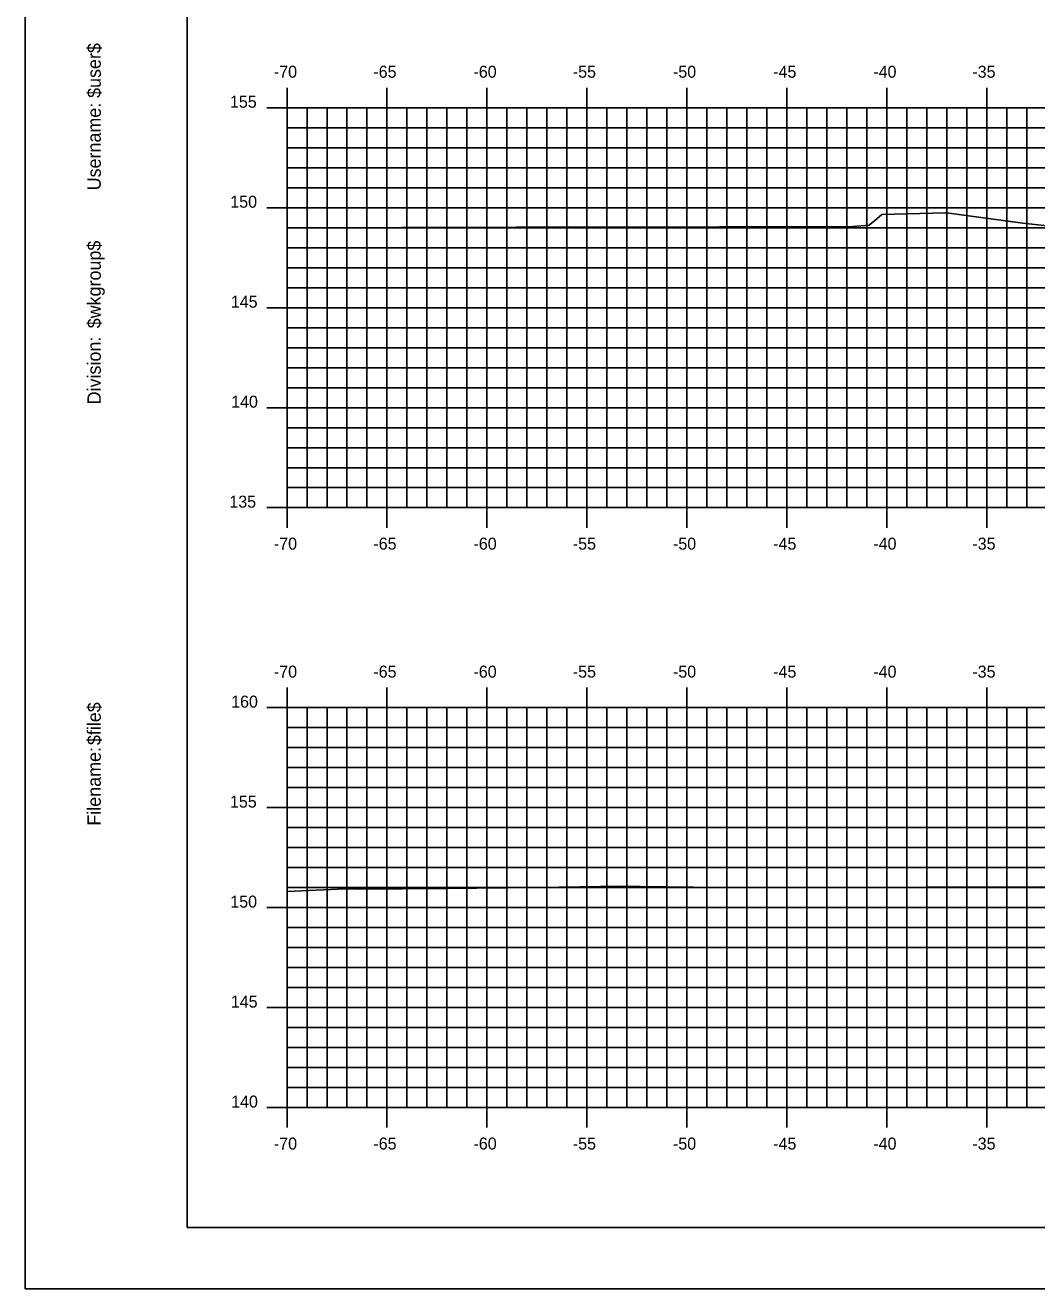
# Model space of a CAD drawing. Extents: x 850973 to 851145, y 365876 to 365986.
# Drawn here: x 850973.3 to 851023.9, y 365875.8 to 365939 of the extents above; entities that cross this region are included whole.
import ezdxf

# ---------------------------------------------------------------- set-up
doc = ezdxf.new("R2010")
doc.units = 0
for name, color, linetype in [('BORDER', 7, 'Continuous'), ('H_V ANNOTATION', 7, 'Continuous'), ('MAJOR', 7, 'Continuous'), ('MINOR', 7, 'Continuous'), ('PLOT BOUNDARY', 7, 'Continuous'), ('S_Roadway_Centerline', 7, 'Continuous')]:
    doc.layers.add(name, color=color, linetype=linetype)

msp = doc.modelspace()

# ---------------------------------------------------------------- linework, layer by layer
at = {"layer": 'BORDER'}
msp.add_lwpolyline([(850981.386, 365878.833), (851141.386, 365878.833), (851141.386, 365983.833), (850981.386, 365983.833)], close=True, dxfattribs=at)
at = {"layer": 'MAJOR'}
for p, q in [((850986.385, 365935.835), (850986.385, 365934.833)), ((850991.385, 365935.835), (850991.385, 365934.833)), ((850996.385, 365935.835), (850996.385, 365934.833)), ((851001.385, 365935.835), (851001.385, 365934.833)), ((851006.385, 365935.835), (851006.385, 365934.833)), ((851011.385, 365935.835), (851011.385, 365934.833)), ((851016.385, 365935.835), (851016.385, 365934.833)), ((851021.385, 365935.835), (851021.385, 365934.833)), ((850985.383, 365934.833), (850986.385, 365934.833)), ((850986.385, 365934.833), (851126.385, 365934.833)), ((850986.385, 365914.833), (850986.385, 365934.833)), ((850986.385, 365914.833), (850986.385, 365934.833)), ((850986.385, 365934.833), (851126.385, 365934.833)), ((850991.385, 365914.833), (850991.385, 365934.833)), ((850996.385, 365914.833), (850996.385, 365934.833)), ((851001.385, 365914.833), (851001.385, 365934.833)), ((851006.385, 365914.833), (851006.385, 365934.833)), ((851011.385, 365914.833), (851011.385, 365934.833)), ((851016.385, 365914.833), (851016.385, 365934.833)), ((851021.385, 365914.833), (851021.385, 365934.833)), ((850985.383, 365929.833), (850986.385, 365929.833)), ((850986.385, 365929.833), (851126.385, 365929.833)), ((850985.383, 365924.833), (850986.385, 365924.833)), ((850986.385, 365924.833), (851126.385, 365924.833)), ((850985.383, 365919.833), (850986.385, 365919.833)), ((850986.385, 365919.833), (851126.385, 365919.833)), ((850985.383, 365914.833), (850986.385, 365914.833)), ((850986.385, 365914.833), (851126.385, 365914.833)), ((850986.385, 365914.833), (851126.385, 365914.833)), ((850986.385, 365913.831), (850986.385, 365914.833)), ((850991.385, 365913.831), (850991.385, 365914.833)), ((850996.385, 365913.831), (850996.385, 365914.833)), ((851001.385, 365913.831), (851001.385, 365914.833)), ((851006.385, 365913.831), (851006.385, 365914.833)), ((851011.385, 365913.831), (851011.385, 365914.833)), ((851016.385, 365913.831), (851016.385, 365914.833)), ((851021.385, 365913.831), (851021.385, 365914.833)), ((850986.385, 365905.835), (850986.385, 365904.833)), ((850991.385, 365905.835), (850991.385, 365904.833)), ((850996.385, 365905.835), (850996.385, 365904.833)), ((851001.385, 365905.835), (851001.385, 365904.833)), ((851006.385, 365905.835), (851006.385, 365904.833)), ((851011.385, 365905.835), (851011.385, 365904.833)), ((851016.385, 365905.835), (851016.385, 365904.833)), ((851021.385, 365905.835), (851021.385, 365904.833)), ((850985.383, 365904.833), (850986.385, 365904.833)), ((850986.385, 365904.833), (851126.385, 365904.833)), ((850986.385, 365884.833), (850986.385, 365904.833)), ((850986.385, 365884.833), (850986.385, 365904.833)), ((850986.385, 365904.833), (851126.385, 365904.833)), ((850991.385, 365884.833), (850991.385, 365904.833)), ((850996.385, 365884.833), (850996.385, 365904.833)), ((851001.385, 365884.833), (851001.385, 365904.833)), ((851006.385, 365884.833), (851006.385, 365904.833)), ((851011.385, 365884.833), (851011.385, 365904.833)), ((851016.385, 365884.833), (851016.385, 365904.833)), ((851021.385, 365884.833), (851021.385, 365904.833)), ((850985.383, 365899.833), (850986.385, 365899.833)), ((850986.385, 365899.833), (851126.385, 365899.833)), ((850985.383, 365894.833), (850986.385, 365894.833)), ((850986.385, 365894.833), (851126.385, 365894.833)), ((850985.383, 365889.833), (850986.385, 365889.833)), ((850986.385, 365889.833), (851126.385, 365889.833)), ((850985.383, 365884.833), (850986.385, 365884.833)), ((850986.385, 365884.833), (851126.385, 365884.833)), ((850986.385, 365884.833), (851126.385, 365884.833)), ((850986.385, 365883.831), (850986.385, 365884.833)), ((850991.385, 365883.831), (850991.385, 365884.833)), ((850996.385, 365883.831), (850996.385, 365884.833)), ((851001.385, 365883.831), (851001.385, 365884.833)), ((851006.385, 365883.831), (851006.385, 365884.833)), ((851011.385, 365883.831), (851011.385, 365884.833)), ((851016.385, 365883.831), (851016.385, 365884.833)), ((851021.385, 365883.831), (851021.385, 365884.833))]:
    msp.add_line(p, q, dxfattribs=at)
at = {"layer": 'MINOR'}
for p, q in [((850987.385, 365914.833), (850987.385, 365934.833)), ((850988.385, 365914.833), (850988.385, 365934.833)), ((850989.385, 365914.833), (850989.385, 365934.833)), ((850990.385, 365914.833), (850990.385, 365934.833)), ((850992.385, 365914.833), (850992.385, 365934.833)), ((850993.385, 365914.833), (850993.385, 365934.833)), ((850994.385, 365914.833), (850994.385, 365934.833)), ((850995.385, 365914.833), (850995.385, 365934.833)), ((850997.385, 365914.833), (850997.385, 365934.833)), ((850998.385, 365914.833), (850998.385, 365934.833)), ((850999.385, 365914.833), (850999.385, 365934.833)), ((851000.385, 365914.833), (851000.385, 365934.833)), ((851002.385, 365914.833), (851002.385, 365934.833)), ((851003.385, 365914.833), (851003.385, 365934.833)), ((851004.385, 365914.833), (851004.385, 365934.833)), ((851005.385, 365914.833), (851005.385, 365934.833)), ((851007.385, 365914.833), (851007.385, 365934.833)), ((851008.385, 365914.833), (851008.385, 365934.833)), ((851009.385, 365914.833), (851009.385, 365934.833)), ((851010.385, 365914.833), (851010.385, 365934.833)), ((851012.385, 365914.833), (851012.385, 365934.833)), ((851013.385, 365914.833), (851013.385, 365934.833)), ((851014.385, 365914.833), (851014.385, 365934.833)), ((851015.385, 365914.833), (851015.385, 365934.833)), ((851017.385, 365914.833), (851017.385, 365934.833)), ((851018.385, 365914.833), (851018.385, 365934.833)), ((851019.385, 365914.833), (851019.385, 365934.833)), ((851020.385, 365914.833), (851020.385, 365934.833)), ((851022.385, 365914.833), (851022.385, 365934.833)), ((851023.385, 365914.833), (851023.385, 365934.833)), ((850986.385, 365933.833), (851126.385, 365933.833)), ((850986.385, 365933.833), (850987.387, 365933.833)), ((850986.385, 365932.833), (851126.385, 365932.833)), ((850986.385, 365932.833), (850987.387, 365932.833)), ((850986.385, 365931.833), (851126.385, 365931.833)), ((850986.385, 365931.833), (850987.387, 365931.833)), ((850986.385, 365930.833), (851126.385, 365930.833)), ((850986.385, 365930.833), (850987.387, 365930.833)), ((850986.385, 365928.833), (851126.385, 365928.833)), ((850986.385, 365928.833), (850987.387, 365928.833)), ((850986.385, 365927.833), (851126.385, 365927.833)), ((850986.385, 365927.833), (850987.387, 365927.833)), ((850986.385, 365926.833), (851126.385, 365926.833)), ((850986.385, 365926.833), (850987.387, 365926.833)), ((850986.385, 365925.833), (851126.385, 365925.833)), ((850986.385, 365925.833), (850987.387, 365925.833)), ((850986.385, 365923.833), (851126.385, 365923.833)), ((850986.385, 365923.833), (850987.387, 365923.833)), ((850986.385, 365922.833), (851126.385, 365922.833)), ((850986.385, 365922.833), (850987.387, 365922.833)), ((850986.385, 365921.833), (851126.385, 365921.833)), ((850986.385, 365921.833), (850987.387, 365921.833)), ((850986.385, 365920.833), (851126.385, 365920.833)), ((850986.385, 365920.833), (850987.387, 365920.833)), ((850986.385, 365918.833), (851126.385, 365918.833)), ((850986.385, 365918.833), (850987.387, 365918.833)), ((850986.385, 365917.833), (851126.385, 365917.833)), ((850986.385, 365917.833), (850987.387, 365917.833)), ((850986.385, 365916.833), (851126.385, 365916.833)), ((850986.385, 365916.833), (850987.387, 365916.833)), ((850986.385, 365915.833), (851126.385, 365915.833)), ((850986.385, 365915.833), (850987.387, 365915.833)), ((850987.385, 365884.833), (850987.385, 365904.833)), ((850988.385, 365884.833), (850988.385, 365904.833)), ((850989.385, 365884.833), (850989.385, 365904.833)), ((850990.385, 365884.833), (850990.385, 365904.833)), ((850992.385, 365884.833), (850992.385, 365904.833)), ((850993.385, 365884.833), (850993.385, 365904.833)), ((850994.385, 365884.833), (850994.385, 365904.833)), ((850995.385, 365884.833), (850995.385, 365904.833)), ((850997.385, 365884.833), (850997.385, 365904.833)), ((850998.385, 365884.833), (850998.385, 365904.833)), ((850999.385, 365884.833), (850999.385, 365904.833)), ((851000.385, 365884.833), (851000.385, 365904.833)), ((851002.385, 365884.833), (851002.385, 365904.833)), ((851003.385, 365884.833), (851003.385, 365904.833)), ((851004.385, 365884.833), (851004.385, 365904.833)), ((851005.385, 365884.833), (851005.385, 365904.833)), ((851007.385, 365884.833), (851007.385, 365904.833)), ((851008.385, 365884.833), (851008.385, 365904.833)), ((851009.385, 365884.833), (851009.385, 365904.833)), ((851010.385, 365884.833), (851010.385, 365904.833)), ((851012.385, 365884.833), (851012.385, 365904.833)), ((851013.385, 365884.833), (851013.385, 365904.833)), ((851014.385, 365884.833), (851014.385, 365904.833)), ((851015.385, 365884.833), (851015.385, 365904.833)), ((851017.385, 365884.833), (851017.385, 365904.833)), ((851018.385, 365884.833), (851018.385, 365904.833)), ((851019.385, 365884.833), (851019.385, 365904.833)), ((851020.385, 365884.833), (851020.385, 365904.833)), ((851022.385, 365884.833), (851022.385, 365904.833)), ((851023.385, 365884.833), (851023.385, 365904.833)), ((850986.385, 365903.833), (851126.385, 365903.833)), ((850986.385, 365903.833), (850987.387, 365903.833)), ((850986.385, 365902.833), (851126.385, 365902.833)), ((850986.385, 365902.833), (850987.387, 365902.833)), ((850986.385, 365901.833), (851126.385, 365901.833)), ((850986.385, 365901.833), (850987.387, 365901.833)), ((850986.385, 365900.833), (851126.385, 365900.833)), ((850986.385, 365900.833), (850987.387, 365900.833)), ((850986.385, 365898.833), (851126.385, 365898.833)), ((850986.385, 365898.833), (850987.387, 365898.833)), ((850986.385, 365897.833), (851126.385, 365897.833)), ((850986.385, 365897.833), (850987.387, 365897.833)), ((850986.385, 365896.833), (851126.385, 365896.833)), ((850986.385, 365896.833), (850987.387, 365896.833)), ((850986.385, 365895.833), (851126.385, 365895.833)), ((850986.385, 365895.833), (850987.387, 365895.833)), ((850986.385, 365893.833), (851126.385, 365893.833)), ((850986.385, 365893.833), (850987.387, 365893.833)), ((850986.385, 365892.833), (851126.385, 365892.833)), ((850986.385, 365892.833), (850987.387, 365892.833)), ((850986.385, 365891.833), (851126.385, 365891.833)), ((850986.385, 365891.833), (850987.387, 365891.833)), ((850986.385, 365890.833), (851126.385, 365890.833)), ((850986.385, 365890.833), (850987.387, 365890.833)), ((850986.385, 365888.833), (851126.385, 365888.833)), ((850986.385, 365888.833), (850987.387, 365888.833)), ((850986.385, 365887.833), (851126.385, 365887.833)), ((850986.385, 365887.833), (850987.387, 365887.833)), ((850986.385, 365886.833), (851126.385, 365886.833)), ((850986.385, 365886.833), (850987.387, 365886.833)), ((850986.385, 365885.833), (851126.385, 365885.833)), ((850986.385, 365885.833), (850987.387, 365885.833))]:
    msp.add_line(p, q, dxfattribs=at)
at = {"layer": 'PLOT BOUNDARY'}
msp.add_lwpolyline([(850973.292, 365875.774), (851143.292, 365875.774), (851143.292, 365985.774), (850973.292, 365985.774)], close=True, dxfattribs=at)
at = {"layer": 'S_Roadway_Centerline'}
for points in [[(850986.385, 365928.832), (850997.86, 365928.864), (851000.484, 365928.869), (851001.333, 365928.852), (851014.684, 365928.898), (851015.507, 365928.967), (851015.893, 365929.281), (851016.145, 365929.486), (851019.302, 365929.578), (851019.379, 365929.574), (851023.183, 365929.056), (851028.186, 365928.504), (851033.588, 365927.674), (851037.474, 365926.925), (851039.808, 365926.786), (851046.433, 365925.629), (851048.76, 365925.118), (851053.69, 365924.218), (851054.402, 365924.069), (851059.389, 365923.99), (851067.935, 365924.248), (851070.348, 365924.286), (851071.299, 365923.923), (851074.89, 365924.107)], [(850986.385, 365895.641), (850989.297, 365895.77), (850989.991, 365895.751), (850994.352, 365895.789), (850998.964, 365895.836), (851003.094, 365895.906), (851004.05, 365895.884), (851009.374, 365895.828), (851018.433, 365895.854), (851023.657, 365895.853), (851035.244, 365895.939)]]:
    msp.add_lwpolyline(points, dxfattribs=at)

# ---------------------------------------------------------------- texts
at = {"layer": 'BORDER'}
for s, p in [('$user$', (850977.07, 365935.325)), ('Username:', (850977.07, 365930.701)), ('$wkgroup$', (850977.07, 365923.803)), ('Division:', (850977.07, 365919.999)), ('$file$', (850977.07, 365902.959)), ('Filename:', (850977.07, 365898.932))]:
    msp.add_text(s, height=0.6696, rotation=90, dxfattribs=at).set_placement(p)
at = {"layer": 'H_V ANNOTATION'}
for s, p in [('-70', (850985.727, 365936.333)), ('-65', (850990.703, 365936.333)), ('-60', (850995.711, 365936.333)), ('-55', (851000.681, 365936.333)), ('-50', (851005.689, 365936.333)), ('-45', (851010.703, 365936.333)), ('-40', (851015.711, 365936.333)), ('-35', (851020.665, 365936.333)), ('155', (850983.531, 365934.833)), ('150', (850983.547, 365929.833)), ('145', (850983.574, 365924.833)), ('140', (850983.59, 365919.833)), ('135', (850983.499, 365914.833)), ('-70', (850985.727, 365912.733)), ('-65', (850990.703, 365912.733)), ('-60', (850995.711, 365912.733)), ('-55', (851000.681, 365912.733)), ('-50', (851005.689, 365912.733)), ('-45', (851010.703, 365912.733)), ('-40', (851015.711, 365912.733)), ('-35', (851020.665, 365912.733)), ('-70', (850985.727, 365906.333)), ('-65', (850990.703, 365906.333)), ('-60', (850995.711, 365906.333)), ('-55', (851000.681, 365906.333)), ('-50', (851005.689, 365906.333)), ('-45', (851010.703, 365906.333)), ('-40', (851015.711, 365906.333)), ('-35', (851020.665, 365906.333)), ('160', (850983.59, 365904.833)), ('155', (850983.531, 365899.833)), ('150', (850983.547, 365894.833)), ('145', (850983.574, 365889.833)), ('140', (850983.59, 365884.833)), ('-70', (850985.727, 365882.733)), ('-65', (850990.703, 365882.733)), ('-60', (850995.711, 365882.733)), ('-55', (851000.681, 365882.733)), ('-50', (851005.689, 365882.733)), ('-45', (851010.703, 365882.733)), ('-40', (851015.711, 365882.733)), ('-35', (851020.665, 365882.733))]:
    msp.add_text(s, height=0.6, dxfattribs=at).set_placement(p)
at = {"layer": 'MAJOR'}
for p in [(850986.381, 365914.833), (850986.381, 365884.833)]:
    msp.add_text('-', height=0.006, dxfattribs=at).set_placement(p)

doc.saveas('drawing.dxf')
